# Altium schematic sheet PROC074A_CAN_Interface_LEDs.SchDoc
size 431 x 279 mm; Date: Not shown in title block; ApprovedBy: Not shown in title block; CheckedBy: Not shown in title block; Author: Not shown in title block; CompanyName: Not shown in title block; Engineer: Not shown in title block; Organization: Not shown in title block; Address1: Not shown in title block; Address2: Not shown in title block; Address3: Not shown in title block; Address4: Not shown in title block; DocumentNumber: 1; Revision: Use project parameter SCH_Rev; SheetNumber: 18; SheetTotal: 22; PageSetup: Record=PageOptions¦CenterHorizontal=True¦CenterVertical=True¦PrintScale=1.00¦XCorrection=1.00¦YCorrection=1.00¦PrintKind=0¦BorderSize=5000000¦LeftOffset=0¦BottomOffset=0¦Orientation=2¦PaperLength=1000¦PaperWidth=1000¦Scale=100¦PaperSource=15¦PrintQuality=600¦MediaType=1¦DitherType=10¦PaperKind=Letter¦PrintScaleMode=1
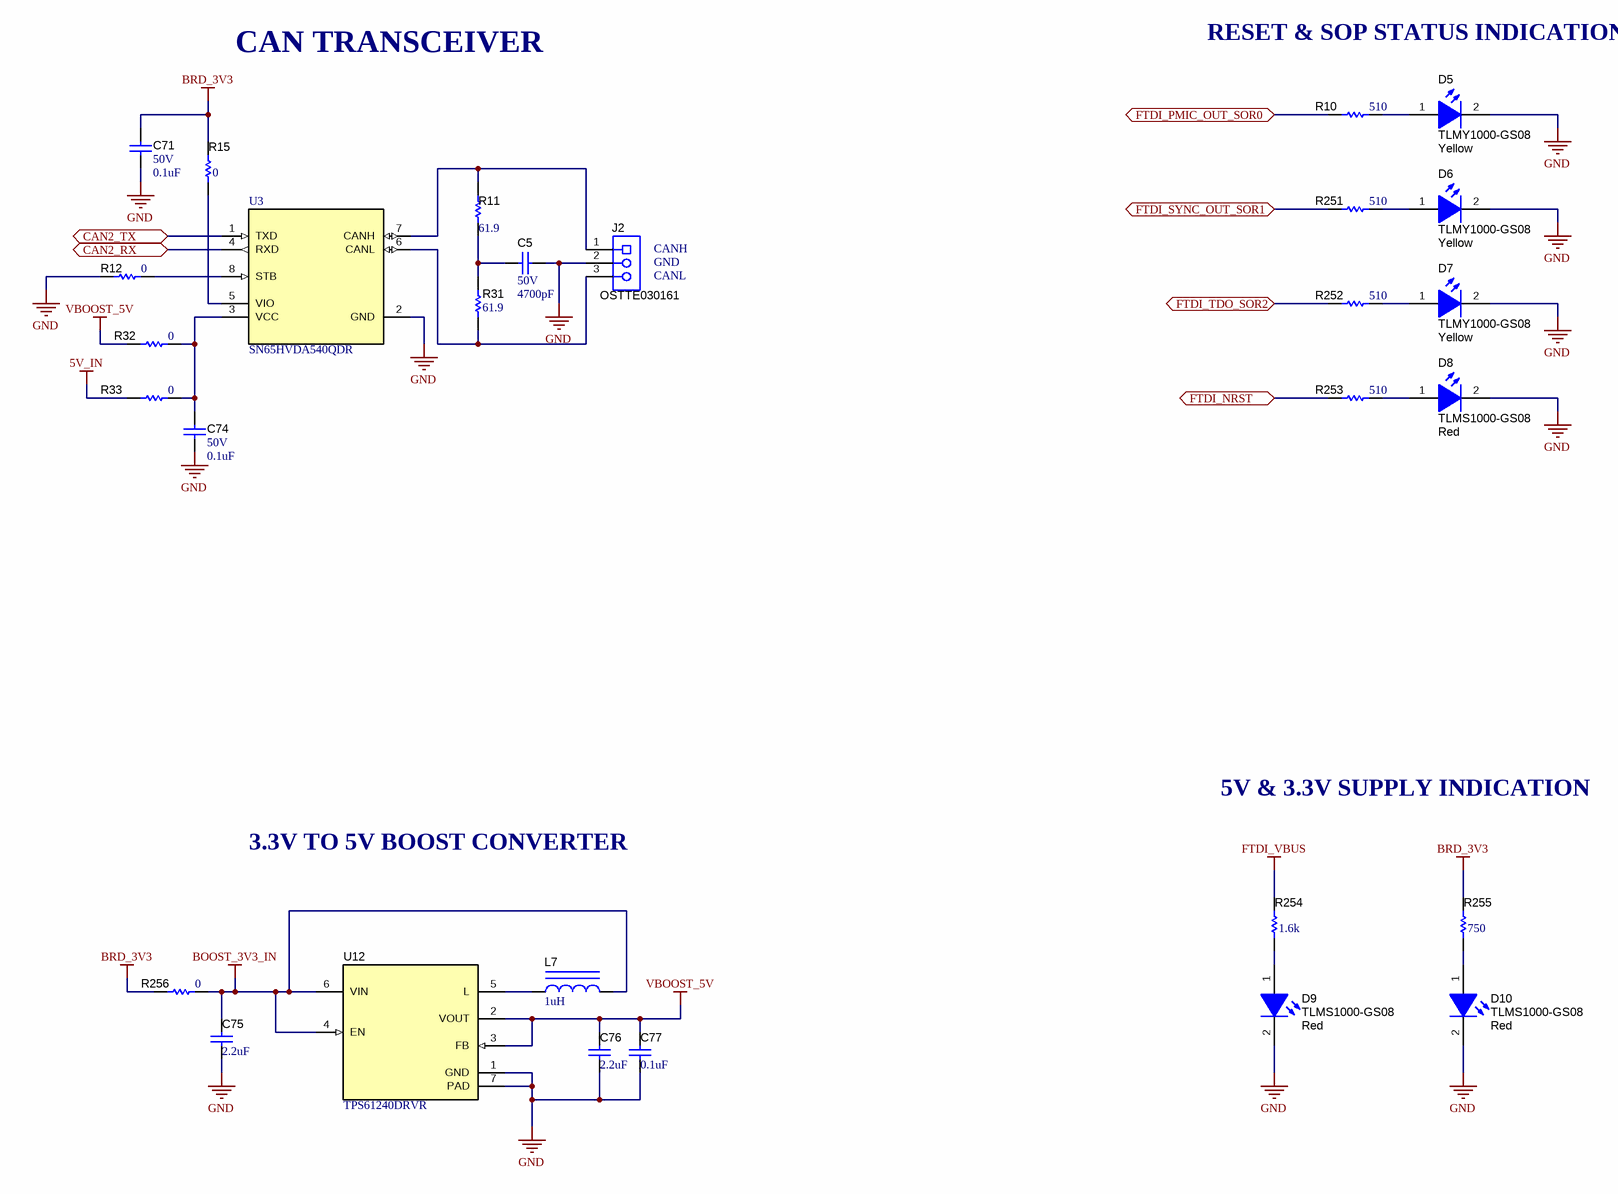
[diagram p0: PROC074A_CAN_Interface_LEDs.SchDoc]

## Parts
C5  VDC_V: 50V  ValueDisplayed: 4700pF  [0402]  (hidden comment: C1005X7R1H472K050BA)
C71  VDC_V: 50V  ValueDisplayed: 0.1uF  [0402]  (hidden comment: CGA2B3X7R1H104K050BB)
C74  VDC_V: 50V  ValueDisplayed: 0.1uF  [0402]  (hidden comment: CGA2B3X7R1H104K050BB)
C75  ValueDisplayed: 2.2uF  [0603]  (hidden comment: C0603C225K8PACTU)
C76  ValueDisplayed: 2.2uF  [0603]  (hidden comment: C0603C225K8PACTU)
C77  ValueDisplayed: 0.1uF  [0402]  (hidden comment: CGA2B3X7R1H104K050BB)
D5  TLMY1000-GS08  value Yellow  [TLMx1000_Yellow]
D6  TLMY1000-GS08  value Yellow  [TLMx1000_Yellow]
D7  TLMY1000-GS08  value Yellow  [TLMx1000_Yellow]
D8  TLMS1000-GS08  value Red  [TLMx1000_Red]
D9  TLMS1000-GS08  value Red  [TLMx1000_Red]
D10  TLMS1000-GS08  value Red  [TLMx1000_Red]
J2  OSTTE030161  [On-Shore_OSTTE030161]
L7  ValueDisplayed: 1uH  [0805_HV]  (hidden comment: LQM21PN1R0MC0D)
R10  ValueDisplayed: 510  [0402]  (hidden comment: ERJ-2GEJ511X)
R11  ValueDisplayed: 61.9  [0402]  (hidden comment: CRCW040261R9FKED)
R12  ValueDisplayed: 0  [0402]  (hidden comment: ERJ-2GE0R00X)
R15  ValueDisplayed: 0  [0402]  (hidden comment: ERJ-2GE0R00X)
R31  ValueDisplayed: 61.9  [0402]  (hidden comment: CRCW040261R9FKED)
R32  ValueDisplayed: 0  [0402]  (hidden comment: ERJ-2GE0R00X)
R33  ValueDisplayed: 0  [0402]  (hidden comment: ERJ-2GE0R00X)
R251  ValueDisplayed: 510  [0402]  (hidden comment: ERJ-2GEJ511X)
R252  ValueDisplayed: 510  [0402]  (hidden comment: ERJ-2GEJ511X)
R253  ValueDisplayed: 510  [0402]  (hidden comment: ERJ-2GEJ511X)
R254  ValueDisplayed: 1.6k  [0402]  (hidden comment: CRCW04021K60JNED)
R255  ValueDisplayed: 750  [0402]  (hidden comment: CRCW0402750RFKED)
R256  ValueDisplayed: 0  [1206]  (hidden comment: CRCW12060000Z0EA)
U3  SN65HVDA540QDR  [D0008A_N]
U12  TPS61240DRVR  [DRV0006A]

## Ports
CAN2_RX, CAN2_TX, FTDI_NRST, FTDI_PMIC_OUT_SOR0, FTDI_SYNC_OUT_SOR1, FTDI_TDO_SOR2

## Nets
5V_IN: R33.1
BOOST_3V3_IN: C75.1 L7.2 R256.2 U12.4(EN) U12.6(VIN)
BRD_3V3: C71.1 R15.2 R255.2 R256.1
FTDI_VBUS: R254.2
GND: C5.1 C71.2 C74.2 C75.2 C76.2 C77.2 D5.2(K) D6.2(K) D7.2(K) D8.2(K) D9.2(K) D10.2(K) J2.2 R12.1 U3.2(GND) U12.1(GND) U12.7(PAD)
VBOOST_5V: C76.1 C77.1 R32.1 U12.2(VOUT) U12.3(FB)
CAN2_RX: U3.4(RXD) ; port CAN2_RX
CAN2_TX: U3.1(TXD) ; port CAN2_TX
FTDI_NRST: R253.1 ; port FTDI_NRST
FTDI_PMIC_OUT_SOR0: R10.1 ; port FTDI_PMIC_OUT_SOR0
FTDI_SYNC_OUT_SOR1: R251.1 ; port FTDI_SYNC_OUT_SOR1
FTDI_TDO_SOR2: R252.1 ; port FTDI_TDO_SOR2
NetC5_2: C5.2 R11.1 R31.2
NetC74_1: C74.1 R32.2 R33.2 U3.3(VCC)
NetD5_1: D5.1(A) R10.2
NetD6_1: D6.1(A) R251.2
NetD7_1: D7.1(A) R252.2
NetD8_1: D8.1(A) R253.2
NetD9_1: D9.1(A) R254.1
NetD10_1: D10.1(A) R255.1
NetJ2_1: J2.1 R11.2 U3.7(CANH)
NetJ2_3: J2.3 R31.1 U3.6(CANL)
NetL7_1: L7.1 U12.5(L)
NetR12_2: R12.2 U3.8(STB)
NetR15_1: R15.1 U3.5(VIO)

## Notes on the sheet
- RESET & SOP STATUS INDICATION
- CAN TRANSCEIVER
- (near J2) CANH
- (near J2) GND
- (near J2) CANL
- 3.3V TO 5V BOOST CONVERTER
- 5V & 3.3V SUPPLY INDICATION

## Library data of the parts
C5 = CMP-0078221-1: CAP, CERM, 4700 pF, 50 V,+/- 10%, X7R, 0402; Manufacturer: TDK; TaMin_C: -55°C; Polarized: N; SizeAreaWB_mm2: 3; U/M: EA; Value: 4700pF; TaMax_C: 125°C; SizeZ_mm: 0.6; SizeX_mm: 1; SizeY_mm: 0.5; Cap_F: 4.7nF; AEC Category: Q200
C71 C74 = CMP-0006325-2: CAP, CERM, 0.1 uF, 50 V, +/- 10%, X7R, AEC-Q200 Grade 1, 0402; Manufacturer: TDK; TaMin_C: -55°C; ESR_ohm: 0.039064; Polarized: N; SizeAreaWB_mm2: 3; Value1: 0.039064 ohm; U/M: EA; Value: 0.1uF; TaMax_C: 125°C; SizeZ_mm: 0.6; SizeX_mm: 1; SizeY_mm: 0.5; AEC Qualified: Y; Cap_F: 100nF; IRMS_A: 8.14669dA; AEC Category: Q200
C75 C76 = CMP-0006906-5: CAP, CERM, 2.2 uF, 10 V, +/- 10%, X5R, 0603; Manufacturer: Kemet; TaMin_C: -55°C; Polarized: N; SizeAreaWB_mm2: 4.68; Value1: Unknown; U/M: EA; Value: 2.2uF; TaMax_C: 85°C; SizeZ_mm: 1; SizeX_mm: 1.6; SizeY_mm: 0.8; Value2: 10V; SizeArea_mm2: 1.28; CompType: Capacitor; Cap_F: 2.2µF; AEC Category: Q200
C77 = CMP-0006325-2: CAP, CERM, 0.1 uF, 50 V, +/- 10%, X7R, AEC-Q200 Grade 1, 0402; Manufacturer: TDK; TaMin_C: -55°C; ESR_ohm: 0.039064; Polarized: N; SizeAreaWB_mm2: 3; Value1: 0.039064 ohm; U/M: EA; Value: 0.1uF; TaMax_C: 125°C; SizeZ_mm: 0.6; SizeX_mm: 1; SizeY_mm: 0.5; Value2: 50V; CompType: Capacitor; AEC Qualified: Y; Cap_F: 100nF; IRMS_A: 8.14669dA; AEC Category: Q200
D5-D7 = CMP-0078196-1: LED, Yellow, SMD; Manufacturer: Vishay-Semiconductor; Tjmax_C: 120°C; SizeAreaWB_mm2: 4.68; Vr_V: 6V; Power_TotalModule: 40mW; Angle: 160; SizeArea_mm2: 1.28; Ir_A: 10µA; SizeZ_mm: 0.65; Io_A: 2mA; Vf_V: 1.8V; SizeY_mm: 0.8; U/M: EA; Value1: .04W; SizeX_mm: 1.6; Type: AlInGaP
D8-D10 = CMP-0078197-1: LED, Red, SMD; Manufacturer: Vishay-Semiconductor; Tjmax_C: 120°C; SizeAreaWB_mm2: 4.68; Vr_V: 6V; Power_TotalModule: 40mW; Angle: 160; SizeArea_mm2: 1.28; Ir_A: 10µA; SizeZ_mm: 0.65; Io_A: 2mA; Vf_V: 1.8V; SizeY_mm: 0.8; U/M: EA; Value1: .04W; SizeX_mm: 1.6; Type: AlInGaP
J2 = CMP-0075352-1: Terminal Block, 3.5mm, 3x1, Tin, R/A, TH; Manufacturer: On-Shore Technology; CNHeader: False; Current_A: 10A; Green_Lifecycle: Not Set; Gender: Female; Cert_CSA: Y; Green_REACh: Incomplete; Voltage_V: 125V; Row_Count: 1; Pitch_mm: 3.5; CT: True
L7 = CMP-0058739-1: Inductor, Multilayer, Ferrite, 1 uH, 0.8 A, 0.19 ohm, SMD; Manufacturer: MuRata; Irms: 0.8A @ 40C rise; Green_Lifecycle: Active; SizeAreaWB_mm2: 6.75; DCR_ohm: 1.9d; Green_REACh: Passed; Value: 1uH; Imax_A: 8dA; SizeZ_mm: 1.45; SizeX_mm: 2; SizeY_mm: 1.25; Value2: 0.8A; SizeArea_mm2: 2.5; Ind_H: 1µH; AEC Category: Q200
R10 R251-R253 = CMP-0078212-1: RES, 510, 5%, 0.1 W, AEC-Q200 Grade 0, 0402; Manufacturer: Panasonic; Value_Code: 510R; SizeArea_mm2: 0.5; AEC Qualified: Y; AEC Category: Q200; Value: 510; SizeZ_mm: 0.6; EIA_Code: E24; TempCo: 200 ppm/C; AEC Grade: 0; Power_W: 100mW; VDC_V: 50V; Value2: 0.1W; U/M: EA; SizeX_mm: 1
R11 R31 = CMP-0026491-2: RES, 61.9, 1%, 0.063 W, AEC-Q200 Grade 0, 0402; Manufacturer: Vishay-Dale; Power_W: 63mW; TempCo: 100 ppm/C; Value_Code: 61R9; Value: 61.9; EIA_Code: E96; SizeX_mm: 1; SizeY_mm: 0.5; SizeZ_mm: 0.6; Value2: 0.063W; AEC Qualified: Y; VDC_V: 50V; AEC Category: Q200; AEC Grade: 0
R12 = CMP-0026992-2: RES, 0, 5%, 0.063 W, 0402; Manufacturer: Panasonic; Power_W: 63mW; TempCo: 600 ppm/C; Value_Code: 0000; U/M: EA; Value: 0; EIA_Code: E24; SizeX_mm: 1; SizeY_mm: 0.5; SizeZ_mm: 0.6; Value2: 0.063W; VDC_V: 50V; AEC Category: Q200
R15 R32 = CMP-0026992-3: RES, 0, 5%, 0.1 W, AEC-Q200 Grade 0, 0402; Manufacturer: Panasonic; Power_W: 100mW; TempCo: 600 ppm/C; Value_Code: 0000; Value: 0; EIA_Code: E24; SizeX_mm: 1; SizeY_mm: 0.5; SizeZ_mm: 0.6; Value2: 0.1W; AEC Qualified: Y; VDC_V: 50V; AEC Category: Q200; SizeAreaWB_mm2: 3
R33 = CMP-0026992-3: RES, 0, 5%, 0.1 W, AEC-Q200 Grade 0, 0402; Manufacturer: Panasonic; Power_W: 100mW; TempCo: 600 ppm/C; Value_Code: 0000; Value: 0; EIA_Code: E24; SizeX_mm: 1; SizeY_mm: 0.5; SizeZ_mm: 0.6; Value2: 0.1W; CompType: Resistor; AEC Qualified: Y; VDC_V: 50V; AEC Category: Q200; SizeAreaWB_mm2: 3; INSTALLATION: DNP
R254 = CMP-0026857-5: RES, 1.6 k, 5%, 0.063 W, AEC-Q200 Grade 0, 0402; Manufacturer: Vishay-Dale; Power_W: 63mW; TempCo: 200 ppm/C; Value_Code: 1k60; Value: 1.6k; EIA_Code: E24; SizeX_mm: 1; SizeY_mm: 0.5; SizeZ_mm: 0.6; Value2: 0.063W; AEC Qualified: Y; VDC_V: 50V; AEC Category: Q200; AEC Grade: 0
R255 = CMP-0026542-2: RES, 750, 1%, 0.063 W, AEC-Q200 Grade 0, 0402; Manufacturer: Vishay-Dale; Power_W: 63mW; TempCo: 100 ppm/C; Value_Code: 750R; Value: 750; EIA_Code: E96; SizeX_mm: 1; SizeY_mm: 0.5; SizeZ_mm: 0.6; Value2: 0.063W; AEC Qualified: Y; VDC_V: 50V; AEC Grade: 0; AEC Category: Q200
R256 = CMP-0018573-3: RES, 0, 5%, 0.25 W, AEC-Q200 Grade 0, 1206; Manufacturer: Vishay-Dale; Power_W: 250mW; TempCo: 200 ppm/C; Value_Code: 0000; Value: 0; EIA_Code: E24; SizeX_mm: 3.2; SizeY_mm: 1.6; SizeZ_mm: 1.35; Value2: 0.25W; SizeArea_mm2: 5.12; AEC Qualified: Y; VDC_V: 200V; AEC Category: Q200
U3 = CMP-0033299-1: 5 V CAN Transceiver with I/O Level Shifting and Supply Optimization, 70 mA, 4.75 to 5.25 V, -40 to 125 degC, 8-pin SOIC (D), Green (RoHS & no Sb/Br); Manufacturer: Texas Instruments; Drivers Per Package: 1; Low Power Mode: Yes; ICC(Max)(mA): 70; Bus Fault Voltage(V): -27 to 40; Rating: Catalog
U12 = CMP-0067209-5: 5V, 400mA, 4MHz Step-Up DC/DC Converter, DRV0006A (WSON-6); Manufacturer: Texas Instruments; Alternate PartNumber: TPS61240DRVT; SizeX_mm: 2; CompType: IC; SizeZ_mm: 0.8; SizeArea_mm2: 4; SizeAreaWB_mm2: 9; U/M: EA; Green_Lifecycle: Active; Green_REACh: Passed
